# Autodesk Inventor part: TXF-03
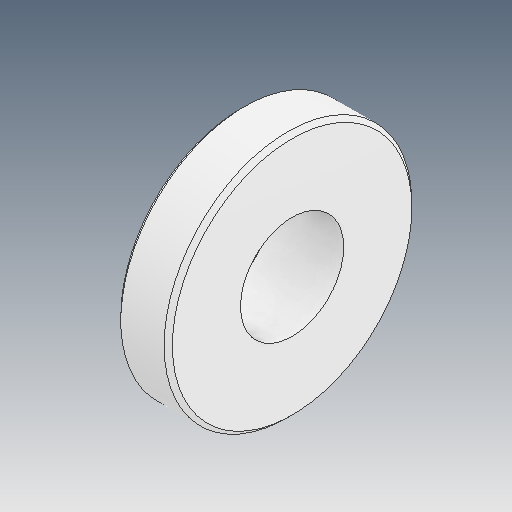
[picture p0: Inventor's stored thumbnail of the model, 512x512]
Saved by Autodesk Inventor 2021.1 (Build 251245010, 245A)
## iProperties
Created: 2021-05
Part Number: TXF-03
Material: Ogólny
Document SubType Name: Modeling
Designer: user
Density: 1 g/cm^3
Appearance: Domyślna
Author: user
Revision Number: ÈÎºÎ
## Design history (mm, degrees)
feature "ÊäÈë1"
node "Bryła1"
